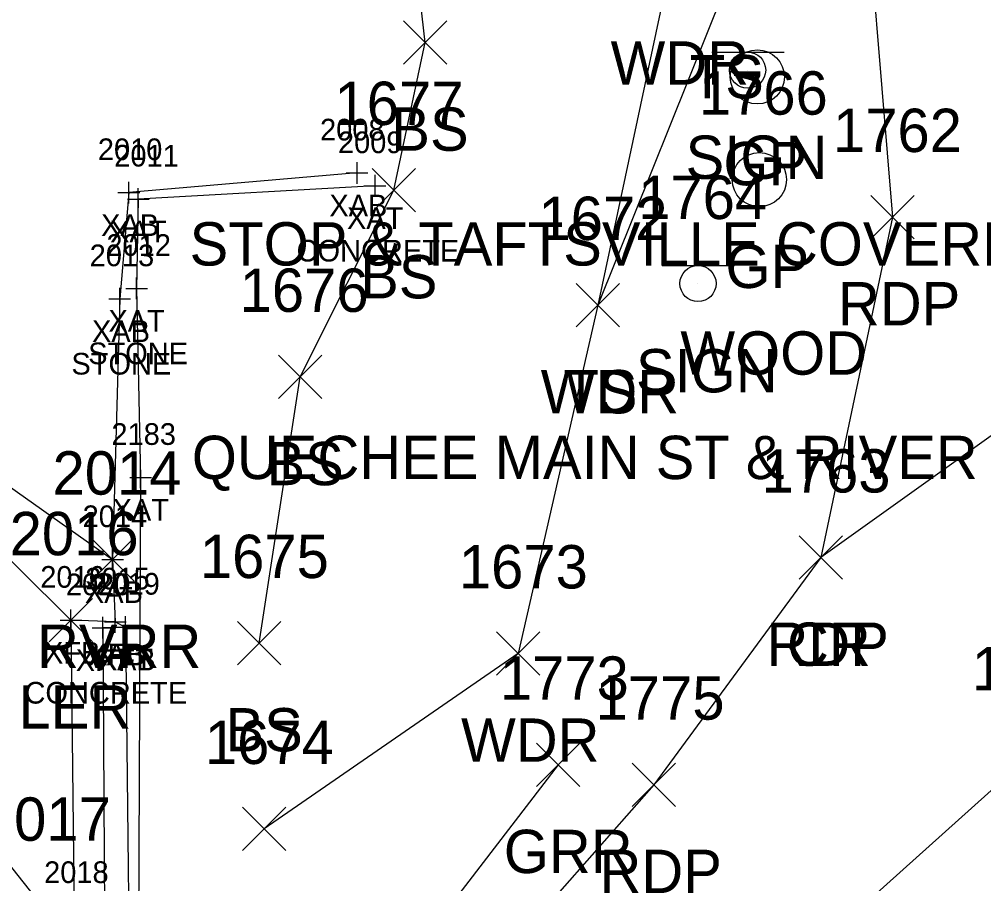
# Model space of a CAD drawing. Extents: x 1647133 to 1649138, y 411736 to 414924.
# Drawn here: x 1648964.63 to 1649009.12, y 412239.42 to 412279.32 of the extents above; entities that cross this region are included whole.
import ezdxf

# ---------------------------------------------------------------- set-up
doc = ezdxf.new("R2010")
doc.units = 0
for name, color, linetype in [('B_A', 7, 'Continuous'), ('B_C', 7, 'Continuous'), ('B_I', 7, 'Continuous'), ('B_TIC', 7, 'Continuous'), ('BFT', 7, 'Continuous'), ('BSUBM', 7, 'Continuous'), ('L_A', 7, 'Continuous'), ('L_I', 7, 'Continuous'), ('L_TIC', 7, 'Continuous'), ('LARO', 7, 'Continuous'), ('LAWA', 7, 'Continuous'), ('LAWE', 7, 'Continuous'), ('LELB', 7, 'Continuous'), ('P_A', 7, 'Continuous'), ('P_I', 7, 'Continuous'), ('P_TIC', 7, 'Continuous'), ('PET', 7, 'Continuous'), ('PRC', 7, 'Continuous'), ('R_A', 7, 'Continuous'), ('R_C', 7, 'Continuous'), ('R_I', 7, 'Continuous'), ('R_TIC', 7, 'Continuous'), ('RGP', 7, 'Continuous'), ('RGR', 7, 'Continuous'), ('S_A', 7, 'Continuous'), ('S_C', 7, 'Continuous'), ('S_I', 7, 'Continuous'), ('SSGN', 7, 'Continuous')]:
    doc.layers.add(name, color=color, linetype=linetype)

msp = doc.modelspace()

# ---------------------------------------------------------------- linework, layer by layer
at = {"layer": 'B_TIC'}
for p, q in [((1648980.215, 412272.224), (1648980.291, 412272.224)), ((1648981.044, 412271.638), (1648981.12, 412271.638)), ((1648969.684, 412271.317), (1648969.76, 412271.317)), ((1648970.116, 412271.021), (1648970.192, 412271.021)), ((1648970.038, 412266.898), (1648970.114, 412266.898)), ((1648969.264, 412266.421), (1648969.34, 412266.421)), ((1648970.229, 412258.175), (1648970.305, 412258.175)), ((1648968.937, 412254.381), (1648969.013, 412254.381)), ((1648967.012, 412251.583), (1648967.087, 412251.583)), ((1648969.056, 412251.503), (1648969.132, 412251.503)), ((1648969.056, 412251.503), (1648969.132, 412251.503)), ((1648968.493, 412251.237), (1648968.568, 412251.237)), ((1648969.529, 412251.264), (1648969.604, 412251.264)), ((1648969.529, 412251.264), (1648969.604, 412251.264))]:
    msp.add_line(p, q, dxfattribs=at)
for points in [[(1648980.212, 412271.724), (1648980.212, 412272.724)], [(1648979.712, 412272.224), (1648980.712, 412272.224)], [(1648981.041, 412271.138), (1648981.041, 412272.138)], [(1648969.681, 412270.817), (1648969.681, 412271.817)], [(1648970.113, 412270.521), (1648970.113, 412271.521)], [(1648980.541, 412271.638), (1648981.541, 412271.638)], [(1648969.181, 412271.317), (1648970.181, 412271.317)], [(1648969.613, 412271.021), (1648970.613, 412271.021)], [(1648970.035, 412266.398), (1648970.035, 412267.398)], [(1648969.261, 412265.921), (1648969.261, 412266.921)], [(1648969.535, 412266.898), (1648970.535, 412266.898)], [(1648968.761, 412266.421), (1648969.761, 412266.421)], [(1648970.226, 412257.675), (1648970.226, 412258.675)], [(1648969.726, 412258.175), (1648970.726, 412258.175)], [(1648968.934, 412253.881), (1648968.934, 412254.881)], [(1648968.434, 412254.381), (1648969.434, 412254.381)], [(1648967.008, 412251.083), (1648967.008, 412252.083)], [(1648969.053, 412251.003), (1648969.053, 412252.003)], [(1648969.053, 412251.003), (1648969.053, 412252.003)], [(1648966.508, 412251.583), (1648967.508, 412251.583)], [(1648968.489, 412250.737), (1648968.489, 412251.737)], [(1648968.553, 412251.503), (1648969.553, 412251.503)], [(1648968.553, 412251.503), (1648969.553, 412251.503)], [(1648969.525, 412250.764), (1648969.525, 412251.764)], [(1648969.525, 412250.764), (1648969.525, 412251.764)], [(1648967.989, 412251.237), (1648968.989, 412251.237)], [(1648969.025, 412251.264), (1648970.025, 412251.264)], [(1648969.025, 412251.264), (1648970.025, 412251.264)]]:
    msp.add_lwpolyline(points, dxfattribs=at)
at = {"layer": 'BFT'}
for points in [[(1648969.053, 412251.503), (1648967.008, 412251.583), (1648967.16, 412237.956), (1648967.307, 412234.686), (1648967.339, 412227.16), (1648986.205, 412204.915), (1649003.564, 412196.539), (1649004.665, 412197.942)], [(1648969.525, 412251.264), (1648968.489, 412251.237), (1648968.622, 412227.573), (1648987.025, 412205.95), (1649003.857, 412197.685), (1649004.163, 412198.216)]]:
    msp.add_lwpolyline(points, dxfattribs=at)
at = {"layer": 'BSUBM'}
for points in [[(1648980.212, 412272.224), (1648969.681, 412271.317), (1648969.261, 412266.421), (1648968.934, 412254.381), (1648969.053, 412251.503), (1648969.525, 412251.264), (1648969.788, 412227.697), (1648987.092, 412207.478), (1648990.118, 412205.514), (1649004.163, 412198.216), (1649004.665, 412197.942), (1649016.348, 412193.098), (1649025.312, 412183.014), (1649046.031, 412166.296)], [(1648981.041, 412271.638), (1648970.113, 412271.021), (1648970.035, 412266.898), (1648970.226, 412258.175), (1648970.119, 412233.914), (1648973.977, 412231.5), (1648974.988, 412233.498)]]:
    msp.add_lwpolyline(points, dxfattribs=at)
at = {"layer": 'L_TIC'}
for points in [[(1648982.349, 412277.248), (1648984.349, 412279.248)], [(1648984.349, 412277.248), (1648982.349, 412279.248)], [(1648980.909, 412270.437), (1648982.909, 412272.437)], [(1648982.909, 412270.437), (1648980.909, 412272.437)], [(1648990.319, 412265.13), (1648992.319, 412267.13)], [(1648992.319, 412265.13), (1648990.319, 412267.13)], [(1648990.319, 412265.13), (1648992.319, 412267.13)], [(1648992.319, 412265.13), (1648990.319, 412267.13)], [(1648976.588, 412261.814), (1648978.588, 412263.814)], [(1648978.588, 412261.814), (1648976.588, 412263.814)], [(1648967.934, 412253.381), (1648969.934, 412255.381)], [(1648969.934, 412253.381), (1648967.934, 412255.381)], [(1648966.008, 412250.583), (1648968.008, 412252.583)], [(1648968.008, 412250.583), (1648966.008, 412252.583)], [(1648974.698, 412249.529), (1648976.698, 412251.529)], [(1648976.698, 412249.529), (1648974.698, 412251.529)], [(1648986.645, 412249.051), (1648988.645, 412251.051)], [(1648988.645, 412249.051), (1648986.645, 412251.051)], [(1648974.929, 412240.95), (1648976.929, 412242.95)], [(1648976.929, 412240.95), (1648974.929, 412242.95)]]:
    msp.add_lwpolyline(points, dxfattribs=at)
at = {"layer": 'LARO'}
msp.add_lwpolyline([(1648937.348, 412344.575), (1648943.966, 412310.574), (1648947.049, 412293.365), (1648952.375, 412266.11), (1648967.008, 412251.583)], dxfattribs=at)
at = {"layer": 'LAWA'}
msp.add_lwpolyline([(1648951.045, 412353.817), (1648963.523, 412336.581), (1648974.712, 412321.819), (1648986.893, 412301.747), (1648993.207, 412292.049), (1648994.543, 412281.301), (1648991.319, 412266.13), (1648987.645, 412250.051), (1648975.929, 412241.95)], dxfattribs=at)
at = {"layer": 'LAWE'}
msp.add_lwpolyline([(1648936.405, 412343.994), (1648939.431, 412308.684), (1648943.855, 412290.757), (1648952.375, 412266.11), (1648968.934, 412254.381)], dxfattribs=at)
at = {"layer": 'LELB'}
for points in [[(1648958.604, 412358.355), (1648969.395, 412339.946), (1648979.597, 412320.412), (1648988.674, 412309.587), (1648996.922, 412293.432), (1648997.149, 412280.665), (1648991.319, 412266.13)], [(1648975.698, 412250.529), (1648977.588, 412262.814), (1648981.909, 412271.437), (1648983.349, 412278.248), (1648982.245, 412288.004), (1648969.913, 412302.757), (1648958.57, 412318.594), (1648952.699, 412330.499)], [(1648921.867, 412322.911), (1648930.857, 412302.743), (1648938.048, 412285.866), (1648946.876, 412268.508), (1648959.298, 412246.43), (1648965.672, 412238.406), (1648966.291, 412234.321)]]:
    msp.add_lwpolyline(points, dxfattribs=at)
at = {"layer": 'P_TIC'}
for points in [[(1649003.904, 412269.19), (1649005.904, 412271.19)], [(1649005.904, 412269.19), (1649003.904, 412271.19)], [(1649000.609, 412253.477), (1649002.609, 412255.477)], [(1649002.609, 412253.477), (1649000.609, 412255.477)], [(1649000.609, 412253.477), (1649002.609, 412255.477)], [(1649002.609, 412253.477), (1649000.609, 412255.477)], [(1648992.905, 412242.995), (1648994.905, 412244.995)], [(1648994.905, 412242.995), (1648992.905, 412244.995)]]:
    msp.add_lwpolyline(points, dxfattribs=at)
at = {"layer": 'PET'}
msp.add_lwpolyline([(1648998.767, 412333.423), (1648994.313, 412324.566), (1648993.834, 412315.066), (1649000.687, 412300.559), (1649003.42, 412288.198), (1649004.904, 412270.19), (1649001.609, 412254.477), (1648993.905, 412243.995), (1648984.626, 412233.464), (1648979.622, 412228.916), (1648985.327, 412222.555), (1648990.487, 412216.934), (1649002.33, 412227.191), (1649016.429, 412237.436), (1649036.674, 412252.918), (1649058.783, 412267.778), (1649074.295, 412277.904), (1649090.06, 412287.47)], dxfattribs=at)
at = {"layer": 'PRC'}
for points in [[(1648967.33, 412365.005), (1648986.07, 412339.485), (1648994.313, 412324.566), (1649012.579, 412298.018), (1649022.055, 412280.385), (1649025.933, 412271.858), (1649001.609, 412254.477)], [(1648985.327, 412222.555), (1648998.031, 412233.463), (1649011.263, 412245.342), (1649030.664, 412261.202), (1649052.944, 412275.662), (1649084.878, 412295.987)]]:
    msp.add_lwpolyline(points, dxfattribs=at)
at = {"layer": 'R_TIC'}
for points in [[(1648988.49, 412243.914), (1648990.49, 412245.914)], [(1648990.49, 412243.914), (1648988.49, 412245.914)]]:
    msp.add_lwpolyline(points, dxfattribs=at)
at = {"layer": 'RGP'}
for p, q in [((1648998.675, 412276.657), (1648998.675, 412276.657)), ((1648998.77, 412271.915), (1648998.77, 412271.915))]:
    msp.add_line(p, q, dxfattribs=at)
for centre, radius in [((1648998.675, 412276.657), 1.25), ((1648998.675, 412276.657), 0.0833), ((1648998.77, 412271.915), 1.25), ((1648998.77, 412271.915), 0.0833)]:
    msp.add_circle(centre, radius, dxfattribs=at)
at = {"layer": 'RGR'}
msp.add_lwpolyline([(1648989.49, 412244.914), (1648979.455, 412231.845)], dxfattribs=at)
at = {"layer": 'SSGN'}
for p, q in [((1648996.58, 412277.805), (1648999.914, 412277.805)), ((1648998.227, 412276.972), (1648998.227, 412276.972)), ((1648994.29, 412267.951), (1648997.623, 412267.951)), ((1648995.937, 412267.118), (1648995.937, 412267.118))]:
    msp.add_line(p, q, dxfattribs=at)
for centre in [(1648998.227, 412276.972), (1648995.937, 412267.118)]:
    msp.add_circle(centre, 0.833, dxfattribs=at)

# ---------------------------------------------------------------- texts
at = {"layer": 'B_A'}
for s, p in [('XAB', (1648978.932, 412270.224)), ('XAT', (1648979.745, 412269.638)), ('XAB', (1648968.401, 412269.317)), ('XAT', (1648968.818, 412269.021)), ('XAT', (1648968.74, 412264.898)), ('XAB', (1648967.981, 412264.421)), ('XAT', (1648968.931, 412256.175)), ('XAB', (1648967.654, 412252.381)), ('XFB', (1648965.768, 412249.583)), ('XFT', (1648967.233, 412249.237)), ('XAB', (1648967.773, 412249.503)), ('XFB', (1648967.813, 412249.503)), ('XAB', (1648968.246, 412249.264)), ('XFT', (1648968.269, 412249.264))]:
    msp.add_text(s, height=1, dxfattribs=at).set_placement(p)
at = {"layer": 'B_C'}
for s, p in [('CONCRETE', (1648977.419, 412268.138)), ('STONE', (1648967.806, 412263.398)), ('STONE', (1648967.032, 412262.921)), ('CONCRETE', (1648964.867, 412247.737))]:
    msp.add_text(s, height=1, dxfattribs=at).set_placement(p)
at = {"layer": 'B_I'}
for s, p in [('2008', (1648978.503, 412273.724)), ('2009', (1648979.328, 412273.138)), ('2010', (1648968.252, 412272.817)), ('2011', (1648969.01, 412272.521)), ('2012', (1648968.649, 412268.398)), ('2013', (1648967.875, 412267.921)), ('2183', (1648968.879, 412259.675)), ('2014', (1648967.548, 412255.881)), ('2016', (1648965.595, 412253.083)), ('2020', (1648966.777, 412252.737)), ('2015', (1648967.667, 412253.003)), ('2015', (1648967.667, 412253.003)), ('2019', (1648968.136, 412252.764)), ('2019', (1648968.136, 412252.764)), ('2018', (1648965.774, 412239.456))]:
    msp.add_text(s, height=1, dxfattribs=at).set_placement(p)
at = {"layer": 'L_A'}
for s, p in [('WDR', (1648991.905, 412276.301)), ('TS', (1648995.558, 412275.665)), ('BS', (1648981.79, 412273.248)), ('BS', (1648980.35, 412266.437)), ('WDR', (1648988.681, 412261.13)), ('TS', (1648989.729, 412261.13)), ('BS', (1648976.029, 412257.814)), ('RVRR', (1648965.446, 412249.381)), ('LER', (1648964.591, 412246.583)), ('BS', (1648974.139, 412245.529)), ('WDR', (1648985.007, 412245.051))]:
    msp.add_text(s, height=2, dxfattribs=at).set_placement(p)
at = {"layer": 'L_I'}
for s, p in [('1677', (1648979.169, 412274.437)), ('1672', (1648988.579, 412269.13)), ('1672', (1648988.579, 412269.13)), ('1676', (1648974.793, 412265.814)), ('2014', (1648966.162, 412257.381)), ('2016', (1648964.182, 412254.583)), ('1675', (1648972.958, 412253.529)), ('1673', (1648984.905, 412253.051)), ('1674', (1648973.189, 412244.95)), ('2017', (1648962.9, 412241.406))]:
    msp.add_text(s, height=2, dxfattribs=at).set_placement(p)
at = {"layer": 'P_A'}
for s, p in [('RDP', (1649002.392, 412265.19)), ('RDP', (1648999.097, 412249.477)), ('CR', (1649000.042, 412249.477)), ('RDP', (1648991.393, 412238.995))]:
    msp.add_text(s, height=2, dxfattribs=at).set_placement(p)
at = {"layer": 'P_I'}
for s, p in [('1762', (1649002.163, 412273.19)), ('1763', (1648998.869, 412257.477)), ('1763', (1648998.869, 412257.477)), ('1784', (1649008.57, 412248.342)), ('1775', (1648991.212, 412246.995))]:
    msp.add_text(s, height=2, dxfattribs=at).set_placement(p)
at = {"layer": 'R_A'}
for s, p in [('GP', (1648997.108, 412271.657)), ('GP', (1648997.203, 412266.915)), ('GRR', (1648986.978, 412239.914))]:
    msp.add_text(s, height=2, dxfattribs=at).set_placement(p)
at = {"layer": 'R_C'}
msp.add_text('WOOD', height=2, dxfattribs=at).set_placement((1648995.124, 412262.915))
at = {"layer": 'R_I'}
for s, p in [('1766', (1648995.975, 412274.915)), ('1773', (1648986.797, 412247.914))]:
    msp.add_text(s, height=2, dxfattribs=at).set_placement(p)
at = {"layer": 'S_A'}
for p in [(1648995.365, 412271.952), (1648993.075, 412262.098)]:
    msp.add_text('SIGN', height=2, dxfattribs=at).set_placement(p)
at = {"layer": 'S_C'}
for s, p in [('STOP & TAFTSVILLE COVERED RD', (1648972.483, 412267.952)), ('QUECHEE MAIN ST & RIVER RD', (1648972.587, 412258.098))]:
    msp.add_text(s, height=2, dxfattribs=at).set_placement(p)
at = {"layer": 'S_I'}
msp.add_text('1764', height=2, dxfattribs=at).set_placement((1648993.177, 412270.098))

doc.saveas('drawing.dxf')
